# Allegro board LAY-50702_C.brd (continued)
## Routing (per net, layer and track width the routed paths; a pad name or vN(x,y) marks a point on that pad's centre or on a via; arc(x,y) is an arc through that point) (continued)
P3V3_BATT: length 17.4
  TOP w0.279: 36.67,37.83 D2.A ; D2.A 36.01,38.66 ; D2.A 36.67,39.48 ; D2.A 37.33,38.66
  BOTTOM w0.279: 38.8,33.37 BT2.1 ; BT2.1 36.78,35.08 ; BT2.1 40.82,35.08 ; BT2.1 38.8,36.8 ; 38.8,37.57 BT1.1 ; BT1.1 36.83,39.08 ; BT1.1 40.77,39.08 ; BT1.1 38.8,40.59
  vias: v1(35.65,38.66) v1(35.65,37.9) v1(35.65,37.13) v1(36.41,37.13)
P3V3_LDO: length 28
  TOP w0.381: D1.C v1(34.26,40.92)
  TOP w0.457: SH19.2 JP19.1
  L3_INT_1 w0.305: v1(34.26,40.92) v1(34.87,40.92) 36.36,39.43 53.31,39.43 JP19.1
P5V: length 53.4
  TOP w0.254: R97.1 v1(20.66,23.52) 20.66,22.94 20.1,22.39 15.76,22.39 14.43,21.06 8.15,21.06 7.73,21.48 D4.C
  TOP w0.279: 21.4,35.49 C23.1 ; C23.1 21.4,37.06 ; C23.1 20.74,36.27 ; TP7.1 21.4,34.97 ; TP7.1 20.68,34.24 ; TP7.1 22.13,34.24 ; TP7.1 21.4,33.52 ; 21.4,38 U4.3 ; U4.3 21.4,39.63 ; U4.3 20.08,38.81 ; U4.3 22.72,38.81
  L4_INT_2 w0.254: v1(22.67,34.24) v1(22.67,33.48) 22.33,33.14 22.2,33.14 21.09,32.02 21.09,30.21 21.57,29.73 21.57,27.92 20.66,27.01 v1(20.66,23.52) 20.66,22.72 20.3,22.36 20.3,18.04 22.35,15.99 v1(22.35,12.2)
  BOTTOM w0.254: SH14.1 v1(22.35,12.2)
  BOTTOM w0.279: D16.C 22.29,33.86 ; D16.C 21.63,33.04 ; D16.C 20.97,33.86 ; D16.C 21.63,34.69
P5V_CAN: length 45.1
  TOP w0.254: v1(15.8,28.9) C111.1 U20.1 15.87,27.88 15.35,27.36 15.35,26.32 15.82,25.85 C103.1 U17.1 15.82,24.83 15.7,24.72 v2(14.82,24.72) 14.13,24.72 11.48,22.07 v1(10.31,22.07)
  TOP w0.279: 15.47,35.01 U18.4 ; U18.4 15.47,37.65 ; U18.4 17.56,36.33 ; U18.4 13.39,36.33 ; 15.47,41.21 U18.2 ; U18.2 15.47,43.85 ; U18.2 14.66,42.53 ; U18.2 16.29,42.53
  L4_INT_2 w0.254: v1(15.8,28.9) 15.8,32.79 v2(18.58,35.57) v2(18.58,36.33) v2(18.58,37.09)
  BOTTOM w0.254: v1(10.31,22.07) C105.1 U19.5
  BOTTOM w0.279: v2(18.58,36.33) 18.58,37.56 ; v2(18.58,36.33) 18.58,35.1 ; v2(18.58,36.33) 19.49,36.33 ; v2(18.58,36.33) 17.66,36.33 ; D16.A 18.58,34.69 ; D16.A 18.58,33.04 ; D16.A 19.24,33.86 ; D16.A 17.92,33.86
P12V: length 17.2
  L4_INT_2 w0.279: J10.3 3.81,24.5 ; J10.3 3.81,22.41 ; J10.3 2.77,23.45 ; J10.3 4.85,23.45 ; 9.87,33.2 J9.1 ; J9.1 9.87,35.08 ; J9.1 11.81,34.14 ; J9.1 7.93,34.14
  BOTTOM w0.279: J9.1 9.87,35.08 ; J9.1 7.93,34.14 ; J9.1 11.81,34.14 ; 12.35,34.14 D8.A ; D8.A 14,34.14 ; D8.A 13.17,34.97
P12V_VBAT: length 6.3
  BOTTOM w0.279: D8.C 13.17,37.77 ; D8.C 13.17,36.12 ; D8.C 12.35,36.94 ; 13.17,37.93 C107.1 ; C107.1 13.17,39.51 ; C107.1 12.51,38.72 ; 13.17,39.58 C108.1 ; C108.1 13.17,40.65 ; C108.1 12.64,40.12
  vias: v2(13.17,43.29) v2(13.17,42.53) v2(13.17,41.77)
VBAT: length 4.9
  TOP w0.457: D2.C C25.1 40.91,41.27 40.92,41.25 JP2.1
VBAT_DCDC/VBAT_PMU: length 12.2
  TOP w0.254: C68.1 C69.1 C72.1
  TOP w0.279: U6.51 43.28,31.22 ; U6.51 43.28,29.33 ; U6.51 43.63,30.28 ; 41.5,36.65 L7.2 ; L7.2 42.92,36.65 ; L7.2 42.21,37.23 ; 43.6,34.85 C68.1 44.26,35.63 ; 43.6,32.18 C72.1 44.26,31.39 ; 44.11,28.5 U6.50 ; 44.11,28 U6.49 ; 43.72,33.45 C69.1
VBUS_USB: length 7.9
  TOP w0.254: J3.1 5.64,15.46 v2(6.21,16.03) L8.1
  BOTTOM w0.254: U9.6 2.91,15.14 3.22,15.45 5.63,15.45 v2(6.21,16.03)
VCC_IF_LINK: length 118.7
  TOP w0.254: v2(45.5,6.77) 44.74,6.01 C91.1 J5.1 46.52,2.67 47.05,2.14 52.05,2.14 52.39,2.48 v1(53.63,2.48) ; SW4.1 58.49,3.81 58.18,3.5 v2(57.69,3.5) ; U15.5 v1(33.93,34.19)
  L3_INT_1 w0.254: v2(57.69,3.5) v2(62.77,3.5) 63.92,3.5 65.79,5.36 v2(66.86,5.36) 68.86,5.36 v1(69.57,4.65) 70.72,3.5 v2(71.92,3.5)
  L4_INT_2 w0.381: v2(45.5,6.77) 45.5,10.04 45.68,10.22 v2(45.68,10.92) 45.68,34.49 46.71,35.52 48.46,35.52 50.01,37.07 50.01,39.61 48.61,41.01 JP18.2
  BOTTOM w0.254: v1(53.63,2.48) C88.1 55.01,2.85 U12.6 55.01,4.22 55.27,4.48 57.44,4.48 57.69,4.22 v2(57.69,3.5) 58.71,2.48 C93.1 59.58,2.85 U14.6 ; C90.1 69.24,2.85 U13.6 69.24,4.32 v1(69.57,4.65)
  BOTTOM w0.279: v2(66.86,5.36) 67.4,5.36 ; v2(66.86,5.36) 66.86,5.89 ; v2(66.86,5.36) 66.33,5.36
  BOTTOM w0.381: JP18.2 48.61,40.11 47.78,39.28 43.74,39.28 43.05,38.59 43.05,34.1 43.79,33.36 43.79,30.67 43.26,30.13 33.53,30.13 33.05,30.62 33.05,33.3 v1(33.93,34.19)
VCC_TGMCU: length 80.3
  TOP w0.305: U16.10 v1(40.73,7.97) ; U16.1 36.82,5.68 v2(36.56,5.42) ; v2(56.92,13.01) 55.86,13.01 55.49,13.38 R67.2 54.53,14.41 54.18,14.77 51.05,14.77 v2(50.1,15.72) ; v2(41.62,4.71) U16.7 40.73,3.59 R101.1 ; U16.15 v1(38.23,7.97)
  TOP w0.457: v2(50.61,40.85) JP18.1
  L3_INT_1 w0.305: v1(40.94,13.35) 42.61,15.02 46.89,15.02 47.57,14.33 49.99,14.33 50.34,14.69 53.97,14.69 55.66,13.01 v2(56.92,13.01) ; v1(38.23,7.97) v1(40.73,7.97)
  L4_INT_2 w0.305: v1(38.23,7.97) 38.23,6.43 37.22,5.42 v2(36.56,5.42) ; v1(40.94,13.35) 40.94,8.69 40.73,8.48 v1(40.73,7.97) 40.73,5.6 v2(41.62,4.71)
  BOTTOM w0.203: v2(56.92,13.01) U11.14
  BOTTOM w0.381: v2(50.1,15.72) 50.1,27.08 47.04,30.14 47.04,35.49 47.75,36.2 49.76,36.2 50.14,36.59 50.14,40.38 v2(50.61,40.85)
VDD_ANA: length 12
  TOP w0.254: U1.29 66.16,19.25 v1(66.3,19.11)
  L3_INT_1 w0.381: JP9.2 70.76,14.1 66.3,18.56 v1(66.3,19.11)
  BOTTOM w0.381: v1(66.3,19.11) 65.87,18.68 C34.1
VDD_CORE: length 32.3
  TOP w0.254: U1.16 60.37,15.27 C14.1 v2(59.61,13.27) ; U1.41 v1(62.37,24.3)
  L4_INT_2 w0.305: v1(62.37,24.3) 61.45,23.38 60.48,23.38 60.1,23 60.1,17.76 60.4,17.45 60.4,15.53 59.97,15.1 59.97,13.63 v2(59.61,13.27)
  BOTTOM w0.381: v1(62.37,24.3) 62.4,24.28 C16.1 C17.1 66.24,24.28 66.63,24.67 66.63,27.26 65.79,28.1 65.79,29.57 67.44,31.22 TP1.1
VDD_DCDC: length 59.6
  TOP w0.254: v2(65.92,12.22) C31.1 64.53,13.24 63.61,14.15 63.61,14.75 62.87,15.49 U1.21
  L4_INT_2 w0.381: v2(65.47,43.25) 66.5,42.21 66.5,35.52 65.26,34.27 65.26,33.03 65.86,32.43 65.86,28.24 67.09,27.01 67.09,24.6 65.59,23.1 64.78,23.1 64.3,22.62 64.3,19.06 66.45,16.91 v2(69.89,16.91) v2(71.16,16.91) 72.12,15.95 72.12,9.13 70.94,7.95 v2(69.24,7.95) 67.93,7.95 66.78,9.1 66.78,11.36 v2(65.92,12.22)
VDD_IC: length 4.7
  L4_INT_2 w0.381: JP2.2 JP2.3
  BOTTOM w0.381: JP2.3 45.19,41.25 45.21,41.27 R107.1
VDD_IO_ABC: length 11.8
  TOP w0.254: U1.4 v1(56.94,21.25)
  TOP w0.305: C32.1 56.88,24.09 v2(56.6,23.81)
  L3_INT_1 w0.254: v2(56.6,23.81) 57.41,23.81 58.1,23.12 58.1,21.82 57.53,21.25 v1(56.94,21.25) 53.39,21.25 JP8.2
VDD_LDO_CORE: length 8.2
  TOP w0.254: U1.15 v1(59.87,15.72)
  BOTTOM w0.254: v1(59.87,15.72) C35.1 58.71,14.33 58.05,14.99 C36.1 C37.1 55.45,14.99 JP4.1
VDD_MEM: length 36.9
  L3_INT_1 w0.381: v1(60.79,41.95) 62.51,41.95 63.45,41.01 v2(63.45,37.14) 67.34,37.14 v2(67.83,37.63) v2(67.83,40.67)
  BOTTOM w0.279: 63.99,37.14 v2(63.45,37.14) 63.45,36.61 ; 67.29,37.63 v2(67.83,37.63) ; v2(67.83,37.63) 67.83,37.09 ; v2(67.83,37.63) 68.36,37.63 ; C44.1 66.84,38.16 ; C44.1 65.77,38.16 ; C44.1 66.3,38.69
  BOTTOM w0.305: v1(60.79,41.95) R19.1
  BOTTOM w0.381: R19.1 52.79,41.19 51.21,39.61 51.21,35.16 50.49,34.44 JS1.1
VDD_PA_2G4: length 10.9
  TOP w0.254: U1.36 65.84,22.75 L2.1
  TOP w0.457: TP3.1 67.5,27.24 66.36,26.09 C7.1 C18.1 L2.1
  TOP w0.508: R89.1 67.83,30.67 67.5,30.34 TP3.1
VDD_REG: length 50.1
  L3_INT_1 w0.381: JP7.1 66.93,11.27 66.93,12.83 68.05,13.95 68.05,15.29 66.45,16.9 59.16,16.9 58.55,17.51 58.55,19.44 58,20 54.14,20 JP8.1
  BOTTOM w0.254: JP9.1 JP7.1
  BOTTOM w0.381: JP10.3 58.68,33.5 55.53,33.5 JP3.2 54.09,29.86 53.45,29.22 53.45,22 54.09,21.37 54.09,19.95 JP8.1
VDD_RF: length 18.3
  TOP w0.254: U1.34 v2(65.82,21.75)
  L3_INT_1 w0.254: v1(68.67,25.41) 67.07,23.81 64.57,23.81 64.22,23.45 64.22,22.05 64.52,21.75 v2(65.82,21.75)
  L4_INT_2 w0.305: v2(66.18,33.56) 68.67,31.07 v1(68.67,25.41)
VDD_SWITCH: length 9.2
  TOP w0.254: v2(56.09,22.54) C26.1 57.1,20.25 U1.6
  BOTTOM w0.381: JP1.1 56.09,25.02 55.58,24.52 55.58,23.04 v2(56.09,22.54)
VOUT_SYS/VDD_SYS: length 3.7
  TOP w0.127: U1.22 v1(63.37,15.72)
  BOTTOM w0.254: C38.1 C39.1 63.12,15.47 v1(63.37,15.72)
ADC0_A13: length 77.6
  L3_INT_1 w0.127: v1(62.37,30.55) 60.28,30.55 59.58,31.25 48.55,31.25 48.19,30.89 26.69,30.89 25.65,29.85 8.78,29.85 v1(7.11,28.18)
  BOTTOM w0.127: v1(62.37,30.55) 63.78,30.55 64.04,30.29 64.04,29.52 62.64,28.13 59.44,28.13 58.45,27.14 58.45,17.42 R8.2 ; SH2.2 v1(7.11,28.18)
ADC_IN: length 1.7
  BOTTOM w0.127: SH2.1 J1.1
ANT: length 2.3
  TOP w0.279: L3.1 L2.2 U1.35
ANT_RF: length 2
  TOP w0.279: L3.2 C1.1 L10.1
BOOT_CFG: length 7.9
  TOP w0.254: v1(53.81,4.3) 54.3,3.81 SW4.2 ; v2(51.01,8.86) 51.98,8.86 52.21,8.63 52.21,8.63 JP16.2
  L4_INT_2 w0.254: v1(53.81,4.3) 53.81,4.78 52.97,5.62 52.97,7.87 JP16.2
CAN_DIR: length 2
  TOP w0.305: U17.5 R97.2
CAN_HI: length 9.1
  TOP w0.279: v1(8.15,25.74) 8.79,26.37 R99.2
  L3_INT_1 w0.102: J10.1 3.81,27.5 3.91,27.4 4.96,27.4 6.15,26.21 6.15,25.8 6.46,25.5 7.54,25.5 7.78,25.74 v1(8.15,25.74)
  BOTTOM w0.279: v1(8.15,25.74) 8.41,25.99 U19.7
CAN_LO: length 9.1
  TOP w0.279: v1(8.15,24.98) 8.79,24.34 R45.1
  L3_INT_1 w0.102: J10.2 3.81,27.02 3.91,27.12 4.85,27.12 5.88,26.09 5.88,25.69 6.34,25.22 7.54,25.22 7.78,24.98 v1(8.15,24.98)
  BOTTOM w0.279: v1(8.15,24.98) 8.41,24.72 U19.6
CAN_RX: length 2.2
  TOP w0.279: U17.3 v1(16.2,23.83)
  BOTTOM w0.279: v1(16.2,23.83) 15.81,23.45 U19.4
CAN_TX: length 2.2
  TOP w0.279: U20.3 v1(16.2,26.88)
  BOTTOM w0.279: v1(16.2,26.88) 15.81,27.26 U19.1
CS: length 5
  BOTTOM w0.127: U5.1 63.97,39.17 64.17,38.97 64.17,38.37 63.96,38.16 R11.2 62.19,38.16 v2(61.8,37.77) R16.2
DBGIF_DETECT: length 1.4
  TOP w0.127: R81.1 U6.78
DBGIF_ISP0_CTRL: length 4.4
  TOP w0.127: U15.2 33.37,33.54 33.69,33.22 33.69,32.7 32.78,31.79 U6.72
DBGIF_RESET: length 50.3
  TOP w0.254: U6.90 v1(30.86,21.5)
  L3_INT_1 w0.127: v1(60.88,4.71) 60.58,4.4 56.03,4.4 53.92,6.51 52.37,6.51 51.49,7.4 49.99,7.4 48.69,8.7 43.71,8.7 43,9.41 37.47,9.41 36.65,8.59 31.83,8.59 31.06,7.83 v1(29.93,7.83)
  L4_INT_2 w0.127: v1(29.93,7.83) 29.93,9.43 30.86,10.36 v1(30.86,21.5)
  BOTTOM w0.127: U14.3 v1(60.88,4.71)
DBGIF_RESET_TXEN: length 55.1
  TOP w0.127: U6.71 v1(33.28,29.04)
  L3_INT_1 w0.127: v2(60.23,2.48) 59.74,1.99 45.16,1.99 44.6,2.55 36.14,2.55 35.64,3.05 v1(34.81,3.05)
  L4_INT_2 w0.127: v1(34.81,3.05) 34.51,3.35 34.51,3.35 33.76,4.1 33.76,28.55 v1(33.28,29.04)
  BOTTOM w0.127: v2(60.23,2.48) U14.5
DBGIF_TCK_SWCLK: length 56.5
  TOP w0.127: v1(42.76,31.53) 42.12,31.53 41.78,31.19 U6.54
  L3_INT_1 w0.127: v1(44.04,2.06) 45.06,1.04 63.7,1.04 64.24,1.58 64.68,1.58 v1(65.22,1.04)
  L4_INT_2 w0.127: v1(44.04,2.06) 44.53,2.55 44.53,8.16 43.82,8.87 43.82,10.63 44.69,11.49 44.69,29.6 v1(42.76,31.53)
  BOTTOM w0.127: U10.2 v1(65.22,1.04)
DBGIF_TDI: length 44.2
  TOP w0.127: U6.7 34.28,13.82 34.55,13.55 35.11,13.55 35.24,13.42 v1(35.24,13.04)
  L4_INT_2 w0.127: v1(64.41,1.04) 36.61,1.04 35.8,1.85 35.8,4.01 35.24,4.58 v1(35.24,13.04)
  BOTTOM w0.127: U10.3 64.72,1.36 v1(64.41,1.04)
DBGIF_TDO_SWO: length 49
  TOP w0.127: U6.83 v1(30.64,25)
  L3_INT_1 w0.127: v1(57.24,5.07) 55.8,5.07 54.03,6.84 52.45,6.84 51.59,7.71 50.34,7.71 49.02,9.03 44.12,9.03 43.36,9.79 37.16,9.79 36.27,8.9 31.46,8.9 v1(30.88,8.33)
  L4_INT_2 w0.127: v1(30.88,8.33) 31.86,9.3 31.86,23.79 v1(30.64,25)
  BOTTOM w0.127: U12.3 56.79,5.79 57.24,5.34 v1(57.24,5.07)
DBGIF_TMS_SWDIO: length 64.1
  TOP w0.127: U6.81 v1(30.64,26)
  L3_INT_1 w0.127: v1(71.08,4.63) 69.43,6.28 65.42,6.28 64.3,5.17 61.82,5.17 60.83,6.16 56.41,6.16 55.37,7.2 52.53,7.2 51.71,8.01 50.6,8.01 49.25,9.36 47.45,9.36 46.63,10.17 31.86,10.17 v1(30.9,9.2)
  L4_INT_2 w0.127: v1(30.9,9.2) 31.53,9.84 31.53,10.16 31.58,10.21 31.58,23.37 30.23,24.72 30.23,25.58 v1(30.64,26)
  BOTTOM w0.127: U13.3 70.54,5.17 v1(71.08,4.63)
DBGIF_TMS_SWDIO_TXEN: length 59.3
  TOP w0.127: U6.66 35.78,29.14 36.23,28.68 v1(39.3,28.68)
  L3_INT_1 w0.127: v2(69.89,2.48) 69.38,2.98 57.08,2.98 53.85,6.21 52.27,6.21 51.36,7.12 49.78,7.12 48.64,8.26 43.54,8.26 43.16,8.64 v1(40.07,8.64)
  L4_INT_2 w0.127: v1(39.3,28.68) 40.74,27.25 40.74,15.21 40.07,14.54 v1(40.07,8.64)
  BOTTOM w0.127: v2(69.89,2.48) U13.5
DBGIF_VREF: length 5.3
  TOP w0.254: U6.23 42.28,13.6 42.89,12.99 C82.1 R44.1 R43.2
DCDC_LX: length 3.8
  TOP w0.254: R1.1 62.71,14.67 62.37,15.01
  TOP w0.279: U1.20 62.37,15.01 ; L1.1 R1.1
EXTAL32K: length 3.1
  TOP w0.127: C50.1 Y2.2 69.99,15.53 69.67,15.21 R31.2
EXTAL_32M: length 1
  L3_INT_1 w0.127: v2(69.63,18.74) v2(69.63,19.76)
EXTAL_RF: length 6.3
  TOP w0.127: U1.33 65.63,21.25 65.9,20.99 v1(65.9,20.99)
  L3_INT_1 w0.127: v1(65.9,20.99) 66.32,20.99 66.53,20.78 v2(69.63,20.78) v2(71.16,20.78)
FL_USB1_DM: length 40.8
  TOP w0.241: U6.35 43.91,21 v1(43.66,21.26)
  BOTTOM w0.241: v1(43.66,21.26) 43.35,20.95 42.06,20.95 41.74,20.63 33.75,20.63 29,15.88 24.78,15.88 23.59,14.69 7.55,14.69 v2(7.23,15.02)
FL_USB1_DP: length 40.8
  TOP w0.241: U6.34 43.91,20.5 v1(43.66,20.24)
  BOTTOM w0.241: v2(7.23,13.96) 7.55,14.28 23.76,14.28 24.95,15.48 29.17,15.48 33.92,20.23 41.91,20.23 42.23,20.55 43.35,20.55 v1(43.66,20.24)
FL_USB_5V0: length 59.4
  TOP w0.279: 10.88,17.1 C75.1 ; C75.1 9.91,17.76 ; C75.1 11.86,17.76 ; v2(12.79,15.85) 12.79,16.9 ; v2(12.79,15.85) 13.28,15.85 ; v2(12.79,15.85) 12.79,14.81 ; D4.A 7.73,19.79 ; D4.A 6.91,19.13 ; D4.A 8.56,19.13 ; D4.A 7.73,18.47 ; C76.1 13.58,17.76 ; C76.1 12,17.76 ; C76.1 12.79,17.1 ; 7.73,16.91 L8.2 ; L8.2 8.36,17.43 ; L8.2 7.11,17.43 ; L8.2 7.73,17.95
  L4_INT_2 w0.305: v2(12.79,15.85) 11.05,15.85 10.45,15.25 10.45,13.45 v2(9.79,12.79)
  BOTTOM w0.305: v1(14.06,17.76) 14.72,17.1 25.86,17.1 26.8,18.04 26.8,21.95 29.14,24.29 42.73,24.29 44.64,26.2 47.2,26.2 47.69,25.71 v2(47.69,24.47)
H/RST: length 3
  BOTTOM w0.127: R18.2 R20.2 66.8,39.67 U5.7
HW_VER_1: length 3.1
  TOP w0.127: R102.1 31.86,32.39 31.86,32.39 32.28,31.97 U6.73
HW_VER_2: length 4.3
  TOP w0.127: U6.65 36.28,31.83 36.74,32.29 38.19,32.29 38.29,32.39 R104.1
HW_VER_3: length 2.1
  TOP w0.127: U6.1 31.28,13.52 31.02,13.26 R105.1
HW_VER_4: length 6.6
  TOP w0.127: R106.1 44.46,15.75 44,16.21 44,18.86 44.14,19 U6.31
HW_VER_6: length 43.7
  TOP w0.127: U6.56 v1(40.78,31.45)
  L4_INT_2 w0.127: JP21.2 47.4,36.36 45.85,36.36 44.78,37.42 42.83,37.42 40.78,35.37 v1(40.78,31.45) 40.78,29.14 43.11,26.8 v1(43.11,6.18)
  BOTTOM w0.127: Q3.1 43.62,7.53 43.11,7.02 v1(43.11,6.18)
HW_VER_7: length 36.6
  TOP w0.127: U6.27 v1(46.27,17) ; JP22.2 65.31,7.31 65.68,6.94 65.69,6.94 66.05,6.58 v1(66.05,3.87)
  L3_INT_1 w0.127: v1(64.62,15.74) 63.42,14.54 59,14.54 57.58,15.96 56.31,15.96 55.42,16.85 49.48,16.85 49.33,17 v1(46.27,17)
  L4_INT_2 w0.127: JP22.2 65.31,11.44 64.62,12.13 v1(64.62,15.74)
  BOTTOM w0.127: v1(66.05,3.87) 64.63,3.87 64.22,4.28 U10.5
HW_VER_8: length 3.7
  TOP w0.127: R96.1 42.21,32.26 41.28,31.33 U6.55
IF_DETECT: length 52.1
  L3_INT_1 w0.127: v1(30.88,7.3) 31.44,7.3 32.26,8.11 34.7,8.11 35.8,7.01 40.52,7.01 41.4,7.88 48.41,7.88 49.45,6.84 51.21,6.84 53.05,5 v2(53.05,4.3)
  L4_INT_2 w0.127: v2(28.08,28.52) 28.08,26.19 31.28,23 31.28,10.27 30.39,9.38 30.39,7.79 v1(30.88,7.3)
  BOTTOM w0.127: v2(53.05,4.3) 52.36,4.3 J5.9 D14.C
IF_ISPEN: length 41.9
  L3_INT_1 w0.127: J5.7 49.69,4.17 46.13,4.17 45.74,3.79 v1(43.62,3.79)
  L4_INT_2 w0.127: v1(43.62,3.79) 43.62,5.01 42.68,5.95 42.68,26.53 38.24,30.97 38.24,31.92 37.57,32.59 37.57,32.59 v2(37.28,32.89)
  BOTTOM w0.127: J5.7 49.44,2.65 48.9,2.65 48.46,2.2 D13.C
IF_TCK_SWDCLK: length 34.8
  TOP w0.127: v2(62.04,5.67) 61.42,6.28 52.15,6.28 51.94,6.49 48.7,6.49 47.79,5.57 J5.4
  L3_INT_1 w0.127: v2(62.04,5.67) 61.14,6.56 56.67,6.56 55.96,7.27 55.96,8.59 55.4,9.15 v1(53.92,9.15)
  BOTTOM w0.127: D15.5 48.71,9.51 48.42,9.22 48.42,7.32 47.79,6.69 R79.1 J5.4 ; v1(53.92,9.15) 53.92,10.96 54.48,11.51 U11.3
IF_TDI: length 23.5
  TOP w0.127: J5.8 50.33,5.57 50.91,6.16 51.82,6.16 52.02,5.95 60.73,5.95 v2(62.04,4.65)
  L4_INT_2 w0.127: J5.8 50.33,6.69 49.87,7.15 49.87,9.24 50.33,9.7 v1(50.33,10.79)
  BOTTOM w0.127: D15.3 47.9,10.16 48.97,11.22 49.9,11.22 v1(50.33,10.79)
IF_TDO_SWO: length 28.8
  L4_INT_2 w0.127: v1(48.29,14.97) 49.41,13.85 v1(49.41,10.79) 49.41,9.73 49.06,9.38 J5.6 49.69,4.17 49.69,2.67 50.37,1.99 56.15,1.99 v2(56.68,1.46)
  BOTTOM w0.127: D15.4 49.41,10.28 v1(49.41,10.79) ; U11.11 54.88,14.14 54.15,14.87 51.1,14.87 51,14.97 v1(48.29,14.97)
IF_TMS_SWDIO: length 53.9
  TOP w0.127: v2(46.52,6.77) J5.2
  L3_INT_1 w0.127: v2(46.52,6.77) 47.85,6.77 48.56,6.07 v1(49.91,6.07) ; v1(46.61,11.84) 47.83,13.06 54.2,13.06 55.07,12.2 v1(58.09,12.2) 58.49,11.79 59.62,11.79 61.07,10.35 65.03,10.35 66.66,8.72 69.85,8.72 72.81,5.76 72.81,2.5 71.77,1.46 v2(70.9,1.46)
  L4_INT_2 w0.127: v1(46.61,11.84) 46.61,9.28 46.02,8.69 46.02,5.3 J5.2
  BOTTOM w0.127: D15.6 49.28,6.7 v1(49.91,6.07) ; v1(58.09,12.2) 56.88,12.2 56.47,12.61 U11.15
IF_TRGRST_SWDRST: length 31.8
  L3_INT_1 w0.127: J5.10 50.68,5.73 50.68,6.18 50.35,6.51 48.87,6.51 v1(47.91,7.46) ; v1(47.25,13.09) 47.58,13.42 50.93,13.42 v1(51.61,14.11)
  L4_INT_2 w0.127: J5.10 52.25,4.16 52.25,3.79 52.55,3.49 56.11,3.49 58.13,1.46 v2(61.25,1.46) ; v1(47.25,13.09) 47.25,11.87 47.91,11.2 v1(47.91,7.46)
  BOTTOM w0.127: v1(51.61,14.11) 51.61,13.42 52.02,13.01 52.95,13.01 U11.7 ; D15.1 47.79,8.86 47.91,8.73 v1(47.91,7.46)
L_R1: length 1.2
  TOP w0.127: LED1.A R22.2
L_Y2: length 1.2
  TOP w0.127: LED2.A R23.2
LED1_R: length 2.3
  TOP w0.127: LED1.C v1(6.85,1.82)
  BOTTOM w0.127: v1(6.85,1.82) 7.38,1.29 Q1.3
LED1_R1: length 2.3
  BOTTOM w0.127: R26.2 R28.2 Q1.1
LED2_Y: length 2.3
  TOP w0.127: LED2.C v1(5.45,1.82)
  BOTTOM w0.127: v1(5.45,1.82) 4.92,1.29 Q2.3
LED2_Y2: length 2.3
  BOTTOM w0.127: R27.1 R29.2 Q2.1
LED_RST: length 1.2
  TOP w0.305: R24.2 D3.A
LLWU/NMI_B: length 1.8
  BOTTOM w0.127: J2.2 SH5.2
LPI2C1_SCL: length 1.8
  BOTTOM w0.127: J2.5 SH11.2
LPI2C1_SDA: length 1.9
  BOTTOM w0.127: J2.6 SH13.2
LPSPI1_PSC0: length 1.7
  BOTTOM w0.127: SH4.1 J1.3
LPSPI1_SCK: length 1.7
  BOTTOM w0.127: SH6.1 J1.4
LPSPI1_SIN: length 1.7
  BOTTOM w0.127: SH8.1 J1.5
LPSPI1_SOUT: length 1.7
  BOTTOM w0.127: SH10.1 J1.6
LPUART0_RX: length 1.8
  BOTTOM w0.127: J2.3 SH7.2
LPUART0_TX: length 1.8
  BOTTOM w0.127: J2.4 SH9.2
MCU_LINK_3V3: length 83.1
  TOP w0.254: v2(28.08,18.02) 28.1,18.04 28.1,18.11 28.49,18.5 U6.96 ; v2(36,12.28) 36,12.94 36.46,13.39 37.74,13.39 38.28,13.93 U6.15 ; U6.95 v2(28.08,19) ; U6.75 v2(31.28,31.71) ; v2(37.28,31.71) U6.63 ; U6.38 46.24,22.5 v2(46.54,22.19) ; v2(28.08,25) 28.58,24.5 U6.84 ; U6.44 46.29,25.5 v2(46.54,25.24) ; v2(34.28,31.71) U6.69
  TOP w0.279: 21.87,14.3 L4.2 ; L4.2 22.44,13.59 ; L4.2 23.01,14.3 ; 26.25,13.4 C51.1 ; C51.1 25.46,14.06 ; C51.1 27.04,14.06 ; C54.1 25.32,14.06 ; C54.1 24.35,13.4 ; C54.1 23.37,14.06
  L3_INT_1 w0.381: v2(46.67,14.31) 43.82,14.31 41.79,12.28 v2(36,12.28) v1(28.08,12.28) ; v2(37.28,31.71) v2(34.28,31.71) v2(31.28,31.71)
  L4_INT_2 w0.381: v1(28.08,12.28) v2(28.08,18.02) v2(28.08,19) v2(28.08,25) 27.09,25.99 27.09,29.2 28.63,30.74 30.31,30.74 v2(31.28,31.71) ; v2(46.67,14.31) 47.35,14.99 47.35,18.42 46.54,19.23 v2(46.54,22.19) 47.12,22.78 47.12,24.66 v2(46.54,25.24)
MCU_LINK_N_16MHZ: length 6.1
  TOP w0.127: C78.1 Y4.1 47.42,18.39 46.53,17.5 U6.28
MCU_LINK_P_16MHZ: length 7.2
  TOP w0.127: U6.29 46.25,18 46.95,18.7 46.95,19.83 47.51,20.39 Y4.2 C77.1
MCU_LINK_RST: length 37.7
  TOP w0.127: U6.32 44.22,19.5 43.53,18.82 v1(43.53,16.47)
  L3_INT_1 w0.127: v1(43.53,16.47) 42.04,16.47 39.83,14.26 26.55,14.26 v1(24.49,12.2)
  L4_INT_2 w0.127: v1(24.49,12.2) 24.49,15.59 21.93,18.14 21.93,23.06 J4.10
MCU_LNK_RX: length 27
  TOP w0.127: v1(37.86,27.91) 35.02,27.91 33.78,29.16 U6.70 ; v1(39.23,8.64) U16.13
  L4_INT_2 w0.127: v1(39.23,8.64) 39.23,14.74 38.8,15.17 38.8,26.97 v1(37.86,27.91)
MCU_LNK_TX: length 28.7
  TOP w0.127: U6.79 33.96,27 34.33,27.36 v1(36.79,27.36) ; v1(38.23,8.64) 38.73,8.14 U16.14
  L4_INT_2 w0.127: v1(36.79,27.36) 37.2,27.36 37.78,26.78 37.78,9.09 v1(38.23,8.64)
MCULINK_VDDA: length 6.6
  TOP w0.254: U6.16 C64.1 C63.1 38.78,10.16 38.9,10.04 R33.1 L5.2
MLINK_3V3: length 150.3
  TOP w0.279: 19.42,15.58 R34.2 18.63,16.25 ; C53.1 20.54,16.25 ; C53.1 19.56,15.58 ; C53.1 21.51,15.58 ; 23.8,17.86 J4.1 24.52,18.58 ; L4.1 23.01,15.99 ; L4.1 21.87,15.99 ; L4.1 22.44,16.7
  TOP w0.305: v1(55.07,6.71) 52.35,6.71 52.17,6.89 47.63,6.89 v1(47.06,7.46) ; v2(36.56,6.43) 36.82,6.18 U16.16 ; R50.1 v1(8.97,6.52)
  TOP w0.381: v2(30.25,32.98) 30.25,34.71 31.8,36.25 37.74,36.25 38.14,36.65 L7.1
  L3_INT_1 w0.305: v1(23.62,32.98) v2(30.25,32.98) ; v1(47.06,7.46) 41.86,7.46 40.83,6.43 v2(36.56,6.43) 19.64,6.43 19.2,6.88 9.33,6.88 v1(8.97,6.52) ; v1(19.39,21.12) 12.56,21.12 11.16,19.72 v1(9.41,19.72)
  L4_INT_2 w0.305: J4.1 24.75,19.53 24.75,24.44 24.13,25.06 v1(23.62,25.06) v1(23.62,32.98) ; v1(9.41,19.72) 9.41,15.93 8.36,14.89 8.36,7.12 v1(8.97,6.52) ; v2(35.96,9.46) 36.56,8.86 v2(36.56,6.43) ; v2(66.86,2.36) 68.21,3.71 68.21,5.91 v2(69.24,6.94)
  BOTTOM w0.279: 66.33,2.36 v2(66.86,2.36) ; v2(66.86,2.36) 66.86,1.83 ; v2(66.86,2.36) 67.4,2.36
  BOTTOM w0.305: R46.1 v1(19.39,21.12) ; U13.1 v2(69.24,6.94) C92.1 U14.1 58,5.79 57.08,6.71 v1(55.07,6.71) 54,6.71 C87.1 54.03,6.31 54.54,5.79 U12.1 ; R47.1 v1(19.31,18.58) ; R48.1 v1(23.62,25.06) ; C83.1 J4.1
MLINK_FB: length 16.9
  TOP w0.127: U6.39 43.91,23 43.55,23.36 43.55,25.64 43.91,26 U6.45 46.2,26 46.45,26.26 C66.1 C65.1 49.05,26.26 49.31,25.99 49.31,24.99 49.44,24.86 L6.2 52,23.73 52.23,23.5 52.87,23.5 53.05,23.33 C67.1
MLINK_LX: length 7.4
  TOP w0.127: U6.48 45.94,27.5 47.11,28.67 L6.1
P_LED: length 17.8
  TOP w0.127: JS2.1 20.35,5.67 20.35,5.9 19.13,7.12 7.44,7.12 R22.1 R23.1 R25.1
P_VDD_SWITCH: length 18.4
  TOP w0.305: JP3.1 52.09,31.09 52.64,30.54 55.06,30.54 JP1.2
  TOP w0.381: v2(45.85,40.25) 46.66,39.43 50.14,39.43 50.8,38.77 50.8,33.34 JP3.1
PIO0_5-ISP_EN: length 1.7
  BOTTOM w0.305: R51.2 J4.7
PIO0_5-ISP_EN-LED_SWD_ACT: length 52.6
  TOP w0.254: v1(30.7,22.5) U6.88
  TOP w0.305: v1(9.94,1.61) 8.55,1.61 8.24,1.91 D7.C ; U6.88 26.86,22.5 v2(25.45,23.91)
  L3_INT_1 w0.305: v1(9.94,1.61) 10.7,0.85 27.66,0.85 v1(28.42,1.61)
  L4_INT_2 w0.305: v1(30.7,22.5) 29.75,21.56 29.75,10.94 28.42,9.61 v1(28.42,1.61)
  BOTTOM w0.305: v2(25.45,23.91) R48.2 25.45,25.69 JP12.2
PIO0_10-SWO: length 32.4
  TOP w0.127: U6.21 v1(41.28,16.45)
  L3_INT_1 w0.127: v1(23.77,12.2) 26.09,14.51 39.33,14.51 v1(41.28,16.45)
  L4_INT_2 w0.127: v1(23.77,12.2) 23.77,15.56 21.55,17.79 21.55,20.7 v2(21.13,21.12)
  BOTTOM w0.127: J4.6 v2(21.13,21.12)
PIO0_11-SWDCLK: length 21.3
  TOP w0.127: U6.13 37.28,16.26 36.41,17.13 35.67,17.13 35.24,17.55 v1(35.24,18.44)
  L3_INT_1 w0.127: v2(21.13,19.85) 21.8,19.19 24.87,19.19 25.11,19.42 34.26,19.42 v1(35.24,18.44)
  BOTTOM w0.127: J4.4 v2(21.13,19.85)
PIO0_12-SWDIO: length 20.3
  TOP w0.127: v1(34.23,18.44) 34.23,17.38 35.03,16.57 36.1,16.57 36.78,15.89 U6.12
  L3_INT_1 w0.127: v2(21.13,18.58) 21.73,17.98 26.72,17.98 27.17,18.44 v1(34.23,18.44)
  BOTTOM w0.127: J4.2 v2(21.13,18.58)
PO_LED: length 1.2
  TOP w0.127: LED3.A R25.2
PTA0/SWD_DIO: length 14.1
  TOP w0.127: U1.8 v1(57.35,19.25)
  L4_INT_2 w0.127: v1(57.35,19.25) 57.77,19.25 58.12,18.89 58.12,17.08 58.45,16.75 58.45,13.37 57,11.91 57,10.7 v1(56.57,10.27)
  BOTTOM w0.127: v1(56.57,10.27) 56.95,10.65 56.95,11.67 56.41,12.21 U11.16
PTA1/SWD_CLK: length 13.2
  TOP w0.127: v1(53.52,11.74) R66.1 ; U1.9 v1(56.89,18.75)
  L4_INT_2 w0.127: v1(53.52,11.74) 53.52,13.01 55.7,15.2 56.69,15.2 57.41,15.92 57.41,17.1 57.82,17.51 57.82,18.25 57.31,18.75 v1(56.89,18.75)
  BOTTOM w0.127: v1(53.52,11.74) 53.81,11.45 53.97,11.45 54.08,11.55 U11.4
PTA4/SWO/BOOT_CFG: length 15
  TOP w0.127: U1.10 56.94,18.25 56.42,17.73 56.42,17.18 56.52,17.08 56.52,17.08 56.9,16.69 56.9,15.93 56.27,15.3 v1(56.27,14.05)
  L4_INT_2 w0.127: JP16.1 54.92,7.92 54.97,7.92 55.93,8.88 55.93,10.25 56.64,10.96 56.64,11.79 56.27,12.17 v1(56.27,14.05)
  BOTTOM w0.127: v1(56.27,14.05) 55.94,14.39 55.4,14.39 55.28,14.27 U11.12
PTA16: length 74.4
  TOP w0.127: U1.11 v1(57.35,17.75)
  L3_INT_1 w0.127: v1(11.23,10.5) 11.23,11.23 13.06,13.06 15.1,13.06 16.42,11.74 17.6,11.74 22.2,16.34 36.96,16.34 37.75,17.13 37.75,17.56 38.08,17.89 49.68,17.89 50.22,17.36 55.73,17.36 56.12,17.75 v1(57.35,17.75)
  L4_INT_2 w0.127: JP13.3 53.12,34.42 53.12,30.34 54.13,29.33 54.13,19.01 54.69,18.45 55.83,18.45 56.53,17.75 v1(57.35,17.75)
  BOTTOM w0.127: v1(11.23,10.5) 11.23,11.07 11.68,11.52 SH7.1
PTA17: length 72.4
  TOP w0.127: U1.12 v1(56.94,17.25)
  L3_INT_1 w0.127: v1(15.41,11.52) 15.93,10.99 18.05,10.99 18.67,11.62 20.38,11.62 24.39,15.63 37.32,15.63 38.62,16.92 41.61,16.92 42.17,17.48 49.56,17.48 49.94,17.1 55.96,17.1 56.1,17.25 v1(56.94,17.25)
  L4_INT_2 w0.127: v1(56.94,17.25) 53.95,17.25 53.53,17.68 53.53,29.08 51,31.61 51,35.54 52.43,36.97 JP14.3
  BOTTOM w0.127: SH9.1 v1(15.41,11.52)
PTA18: length 34
  TOP w0.127: U1.13 v1(58.87,15.72) ; U2.17 76.65,24.98 76.52,25.11 v1(76.15,25.11)
  L3_INT_1 w0.127: v1(60.87,28.61) 62,27.49 68.71,27.49 69.46,28.24 v1(71.23,28.24)
  L4_INT_2 w0.127: v1(60.87,28.61) 60.27,28.02 60.27,27.59 58.48,25.8 58.48,17.36 58.87,16.96 v1(58.87,15.72)
  BOTTOM w0.127: v1(76.15,25.11) 75.49,25.11 74.15,26.45 74.15,27.64 73.56,28.24 C100.1 R94.1 v1(71.23,28.24)
PTA19: length 34.8
  TOP w0.127: U1.14 v1(59.37,15.32) ; U2.18 75.79,24.4 R91.2 v2(73.99,25.19)
  L3_INT_1 w0.127: v1(72.52,29.02) 72.21,28.71 68.92,28.71 68.03,27.82 62.67,27.82 v1(61.87,28.61)
  L4_INT_2 w0.127: v1(72.52,29.02) 73.34,29.02 73.99,28.38 v2(73.99,25.19) ; v1(59.37,15.32) 59.37,17.07 58.88,17.56 58.88,25.63 v1(61.87,28.61)
PTA20: length 40.1
  TOP w0.127: U2.19 74.41,23.75 v2(72.97,25.19) ; U1.17 v1(60.87,15.32)
  L3_INT_1 w0.127: v1(72.72,30.04) 71.8,29.12 68.64,29.12 67.77,28.25 66.1,28.25 65.74,28.61 v1(63.84,28.61)
  L4_INT_2 w0.127: v1(63.84,28.61) 63.02,27.79 63.02,24.27 61.11,22.36 61.11,16.38 60.87,16.14 v1(60.87,15.32)
  BOTTOM w0.127: v1(72.72,30.04) 72.1,29.42 69.76,29.42 68.61,28.28 68.61,26.55 69.98,25.19 R95.1 v2(72.97,25.19)
PTA21: length 2.6
  TOP w0.127: v1(61.37,15.72) U1.18
  BOTTOM w0.127: R8.1 U1.18 v1(61.37,15.72)
PTB0: length 63.6
  TOP w0.127: v1(59.87,30.06) U1.46
  L3_INT_1 w0.127: v1(59.87,30.06) 59.21,30.72 54.11,30.72 53.78,30.39 26.9,30.39 25.86,29.35 13.35,29.35 v1(12.19,28.18)
  L4_INT_2 w0.127: v1(59.87,30.06) 61.07,31.25 61.07,33.66 60.79,33.95 v1(60.79,35.74)
  BOTTOM w0.127: R16.1 v1(60.79,35.74) ; SH4.2 v1(12.19,28.18)
PTB1: length 68.1
  TOP w0.127: v1(59.77,39.16) 58.72,38.11 58.72,29.81 59.37,29.16 v1(59.37,25.19) U1.47
  L3_INT_1 w0.127: v1(22.35,28.18) 26.8,28.18 27.49,27.49 v1(33.21,27.49) ; v1(59.37,25.19) 52.24,25.19 48.78,21.73 45.35,21.73 44.84,22.23 42.88,22.23 41.3,20.65 34.05,20.65 v1(33.21,21.48)
  L4_INT_2 w0.127: v1(33.21,27.49) v1(33.21,21.48)
  BOTTOM w0.127: v1(22.35,28.18) 19.98,28.18 SH8.2 ; R13.1 v1(59.77,39.16)
PTB2: length 75.5
  TOP w0.127: U1.48 58.87,27.52 v1(57.78,28.61) ; v2(69.86,39.66) 70.59,38.92 70.59,33.94 71.3,33.24 v1(71.3,30.04)
  L3_INT_1 w0.127: v1(71.3,30.04) 69.72,30.04 69.22,30.54 63.05,30.54 62.57,30.06 62.26,30.06 61.78,29.57 58.74,29.57 v1(57.78,28.61) 54.92,28.61 53.4,30.13 27,30.13 25.96,29.09 16.75,29.09 15.84,28.18 v1(14.73,28.18)
  BOTTOM w0.127: SH6.2 v1(14.73,28.18)
PTB3: length 73
  TOP w0.127: v1(57.78,27.9) 58.25,27.43 58.25,24.37 57.44,23.55 57.44,22.85 57.54,22.75 U1.1 ; v2(69.86,40.67) 70.95,39.58 70.95,34.27 72.01,33.21 v1(72.01,30.04)
  L3_INT_1 w0.127: v1(20.83,28.61) 25.84,28.61 27.11,29.88 53.2,29.88 54.85,28.23 57.46,28.23 v1(57.78,27.9) 59.27,27.9 60.41,29.04 63.2,29.04 64.26,30.09 68.88,30.09 69.45,29.53 71.5,29.53 v1(72.01,30.04)
  BOTTOM w0.127: SH10.2 v1(20.83,28.61)
PTB4: length 90.4
  TOP w0.127: v2(61.8,36.75) 60.06,36.75 v1(59.27,37.55) ; U1.2 v1(56.94,22.25)
  L3_INT_1 w0.127: v1(56.94,22.25) 56.64,22.55 56.64,22.95 56.34,23.25 51.32,23.25 48.83,20.76 43.11,20.76 42.27,19.92 25.08,19.92 24.52,20.48 15.36,20.48 v1(14.73,19.85) ; v2(69.86,38.64) 69.86,37.88 68.1,36.13 62.43,36.13 v2(61.8,36.75)
  L4_INT_2 w0.127: v1(14.73,19.85) 14.73,13.74 13.62,12.63 13.62,6.06 JP24.3 ; v1(56.94,22.25) 57.67,22.98 57.67,25.87 58.99,27.19 58.99,33.28 59.27,33.56 v1(59.27,37.55)
PTB5: length 67.9
  TOP w0.127: U1.3 v1(57.35,21.75)
  L3_INT_1 w0.127: v1(57.35,21.75) 52,21.75 49.23,18.98 37.07,18.98 36.76,18.68 36.76,17.81 36,17.05 22.13,17.05 v1(17.27,12.2)
  L4_INT_2 w0.127: v1(58.75,40.17) 59.27,39.66 59.27,38.62 59.72,38.16 59.72,33.28 59.37,32.93 59.37,27.12 58.07,25.82 58.07,22.48 v1(57.35,21.75)
  BOTTOM w0.127: R15.1 v1(58.75,40.17) ; SH11.1 v1(17.27,12.2)
PTC0: length 79.9
  TOP w0.127: U1.37 64.37,24.35 64.68,24.66 v1(64.68,25.19)
  L3_INT_1 w0.127: JP23.3 14.56,3.95 30.56,3.95 31.42,4.81 33.48,4.81 33.93,4.35 35.41,4.35 35.84,3.92 40.49,3.92 41.48,2.93 45.42,2.93 46,2.35 52.6,2.35 54.44,4.19 v1(54.44,4.81)
  L4_INT_2 w0.127: v1(54.44,4.81) 56.18,6.55 56.18,9.41 56.54,9.76 58.7,9.76 60.35,11.41 60.35,12.4 62.18,14.23 62.18,22.69 v1(64.68,25.19)
  BOTTOM w0.127: JP23.3 12.73,3.06 12.53,3.26 11.71,3.26 10.44,4.53 10.44,5.19 10.05,5.58 R26.1
PTC1: length 25.5
  TOP w0.127: v2(63.82,42.23) R9.2 C45.1 TP9.1 ; U1.38 v1(63.87,25.19)
  L4_INT_2 w0.127: v2(63.82,42.23) 63.82,38.81 64.41,38.21 64.41,36.81 63.04,35.44 63.04,31.17 64.26,29.96 64.26,28.02 63.87,27.64 v1(63.87,25.19)
PTC2: length 18.7
  TOP w0.127: v1(63.37,30.04) C21.1 U1.39
  L4_INT_2 w0.127: JP13.1 58.19,34.43 58.19,30.86 v1(57.36,30.04)
  BOTTOM w0.127: v1(63.37,30.04) 62.24,30.04 61.78,29.57 58.71,29.57 58.24,30.04 v1(57.36,30.04)
PTC3: length 20.8
  TOP w0.127: v1(62.37,29.53) C22.1 62.87,25.83 U1.40
  L4_INT_2 w0.127: JP14.1 57.51,36.89 58.61,35.8 58.61,30.35 v1(57.78,29.53)
  BOTTOM w0.127: v1(62.37,29.53) 61.98,29.14 58.17,29.14 v1(57.78,29.53)
PTC4: length 47.5
  TOP w0.279: v1(62.01,25.19) 62.01,24.78 61.87,24.64 U1.42
  L3_INT_1 w0.102: v1(62.01,25.19) 62.01,25.56 61.76,25.81 61.76,26.07 61.33,26.5 43.89,26.5 41.72,24.33 27.5,24.33 27.2,24.62 22.78,24.62 22.42,24.98 19.75,24.98 19.65,25.08 v2(19.65,26.37)
PTC5: length 47.1
  TOP w0.279: U1.43 61.37,24.64 61.24,24.78 v1(61.24,25.19)
  L3_INT_1 w0.102: v1(61.24,25.19) 61.24,25.56 61.48,25.81 61.48,25.95 61.21,26.22 44.01,26.22 41.84,24.05 27.38,24.05 27.09,24.34 22.67,24.34 22.31,24.7 19.75,24.7 19.65,24.6 v2(19.65,23.32)
PTC6: length 75.4
  TOP w0.127: U1.44 v1(60.87,24.3)
  L3_INT_1 w0.127: v1(6.26,21.4) 10.52,21.4 11.44,22.31 20.94,22.31 21.62,22.99 25.15,22.99 25.46,23.3 33.38,23.3 33.74,22.94 41.97,22.94 42.73,23.71 48.6,23.71 50.6,25.71 60.57,25.71 60.79,25.48 60.79,24.84 60.87,24.76 v1(60.87,24.3)
  L4_INT_2 w0.127: v1(6.26,21.4) 6.26,18.91 5.47,18.12 5.47,9.87 v1(4.32,8.72)
  BOTTOM w0.127: R27.2 v1(4.32,8.72)
PTC7: length 92.4
  TOP w0.127: U1.45 v1(60.37,25.19) 60.37,30.21 59.11,31.48 59.11,35.09 60.3,36.28 66.55,36.28 66.98,36.71 66.98,38.79 TP12.1 68.35,40.16 68.35,41.4 68.67,41.71 C46.1 R17.2 SW3.2
  L3_INT_1 w0.127: v1(13.22,21.72) 24.98,21.72 26.42,20.28 41.84,20.28 43.26,21.7 44.51,21.7 44.97,21.24 48.83,21.24 52.33,24.74 59.92,24.74 v1(60.37,25.19)
  L4_INT_2 w0.127: v1(8.97,11.52) 8.97,13.62 9.71,14.36 9.71,15.32 10.35,15.96 10.35,18.85 v1(13.22,21.72)
  BOTTOM w0.127: SH5.1 v1(8.97,11.52)
PTD2: length 63.1
  TOP w0.127: v1(65.9,15.17) 65.9,17.06 65.71,17.25 U1.25
  L3_INT_1 w0.127: v1(65.9,15.17) 65.1,15.17 64.06,14.13 58.7,14.13 57.23,15.6 56.13,15.6 55.14,16.59 48.89,16.59 48.23,15.93 42.04,15.93 40.11,14 27.13,14 24.39,11.26 21.11,11.26 20.5,10.65 v1(19,10.65)
  L4_INT_2 w0.127: JP23.1 19,4.38 v1(19,10.65)
PTD2/TMP1_CH0: length 10.1
  BOTTOM w0.127: JP23.2 14.73,3.51 14.38,3.87 11.99,3.87 11.07,4.78 11.07,6.01 10.14,6.94 SH3.1
PTD3: length 61.5
  TOP w0.127: U1.26 65.73,17.75 66.33,17.15 66.33,14.98 v1(66.71,14.6)
  L3_INT_1 w0.127: v1(66.71,14.6) 65.39,14.6 64.54,13.75 58.47,13.75 57.07,15.15 48.98,15.15 48.6,15.53 42.15,15.53 40.37,13.75 27.62,13.75 24.67,10.8 21.39,10.8 20.62,10.04 v1(18.29,10.04)
  L4_INT_2 w0.127: v1(18.29,10.04) 18.29,6.72 JP24.1
PTD3/I2C1_SDA: length 5.5
  BOTTOM w0.127: SH13.1 15.26,6.87 14.73,6.33 JP24.2
PTD4_XTAL32K: length 6
  TOP w0.127: R30.1 67.6,14.96 67.6,15.35 67.09,15.86 67.09,17.6 66.44,18.25 U1.27
PTD5_EXTAL32K: length 5.6
  TOP w0.127: U1.28 66,18.75 66.14,18.6 66.56,18.6 67.42,17.74 67.42,16 R31.1
PWM/TMP1_CH0: length 1.8
  BOTTOM w0.127: SH3.2 J2.1
RESET: length 1.7
  BOTTOM w0.127: SH1.1 J1.2
RF1: length 2.3
  TOP w0.279: U2.14 R110.1 R92.1
RF4: length 2.3
  TOP w0.279: U2.5 C98.1 R93.1
RF_50: length 2
  TOP w0.279: C3.1 C2.1 L10.2
RF_A: length 16.5
  TOP w0.279: U2.11 79.75,23.25 arc(81.86,24.12) 82.73,26.23 arc(83.06,27.67) 83.89,28.89 C9.1 L11.1
RF_ANT_1: length 3.1
  TOP w0.279: E1.1 C10.1 L11.2
RF_ANT_2: length 3.1
  TOP w0.279: E2.1 C12.1 L12.2
RF_B: length 16.5
  TOP w0.279: L12.1 C11.1 83.89,16.11 arc(83.06,17.33) 82.73,18.77 arc(81.86,20.88) 79.75,21.75 U2.8
RF_SMA_1: length 2.4
  TOP w0.279: J7.1 C97.1 R92.2
RF_SMA_2: length 2.4
  TOP w0.279: R93.2 C99.1 J8.1
RST_TGTMCU_B: length 104.7
  TOP w0.127: SW1.2 69.69,3.81 70.33,4.45 70.33,5.69 71.51,6.87 73.74,6.87 74.48,7.6 74.48,10.8 JP11.2 ; U1.23 63.87,15.21 65.06,14.03 v1(65.9,14.03)
  L3_INT_1 w0.127: v1(49.74,30.83) 49.32,30.83 49.13,30.64 26.79,30.64 25.75,29.6 11.07,29.6 v1(9.65,28.18) ; v1(52.88,14.11) 53.54,13.45 54.46,13.45 55.35,12.56 57.61,12.56 57.9,12.85 64.72,12.85 v1(65.9,14.03)
  L4_INT_2 w0.127: JP25.2 54.02,11.31 53.31,11.31 53.09,11.54 53.09,12.66 52.88,12.86 v1(52.88,14.11) 52.88,14.56 52.65,14.79 51.89,14.79 51.51,15.17 51.51,16.27 49.74,18.04 v1(49.74,30.83)
  BOTTOM w0.127: JP11.2 71.25,14.03 v1(65.9,14.03) ; SH1.2 v1(9.65,28.18)
RST_U11: length 5.9
  L4_INT_2 w0.127: v1(52.25,14.11) 52.25,12.86 52.1,12.71 52.1,11.23 JP25.1
  BOTTOM w0.127: v1(52.25,14.11) 52.25,13.65 52.49,13.41 52.95,13.41 U11.8
SCK: length 6.9
  L3_INT_1 w0.127: v2(68.84,39.66) 69.35,40.17 71.26,40.17 71.6,39.82 v2(71.6,38.77)
  BOTTOM w0.127: v2(68.84,39.66) R10.2 67.31,40.17 U5.6
SI: length 9.7
  L3_INT_1 w0.127: v2(68.84,40.67) 69.45,41.28 72.58,41.28 73.03,40.83 v2(73.03,38.77)
  BOTTOM w0.127: v2(68.84,40.67) 68.26,41.26 67.47,41.26 66.89,40.67 U5.5
SO: length 1.9
  BOTTOM w0.127: U5.2 62.32,39.67 v2(61.8,39.16)
SW_50: length 0.9
  TOP w0.279: U2.22 C3.2
SWITCH_WAKEUP_B: length 19.9
  TOP w0.127: U1.5 v1(57.35,20.75)
  L3_INT_1 w0.127: TP4.1 v1(57.78,27.16)
  BOTTOM w0.127: v1(57.78,27.16) 57.78,21.18 v1(57.35,20.75)
USB1_VBUS: length 5.2
  TOP w0.127: U6.36 47.18,21.5 47.69,22 R37.2 R41.1
V_BRD: length 161.1
  TOP w0.305: R91.1 76.08,26.2 v1(76.41,25.88) 77.15,25.14 U2.16 ; v2(18.63,25.35) 18.12,24.83 U17.6 ; U20.6 v2(18.63,27.88) ; R17.1 v1(70.41,43.25)
  TOP w0.457: SH19.1 55.55,41.92 55.15,42.32 JP19.2
  L3_INT_1 w0.381: JP2.4 45.48,41.79 53.67,41.79 JP19.2
  L4_INT_2 w0.305: 20.29,42.91 19.39,42.01 19.39,33.28 18.63,32.53 v2(18.63,27.88) v2(18.63,25.35) 18.63,15.93 21.29,13.27 21.29,7.45 22.35,6.38 JS2.2
  L4_INT_2 w0.381: JP2.4 45.52,41.76 45.52,40.78 44.35,39.61 39.07,39.61 35.76,42.91 20.29,42.91 ; v1(70.41,43.25) 69.8,43.85 60.58,43.85 58.75,42.02 56.39,42.02 JP19.2 50.98,39.1 50.98,36.69 50.06,35.77 50.06,33.01 49.5,32.44 JS1.2 48.83,17.19 49.08,16.94 v2(49.08,15.72)
  BOTTOM w0.381: v1(70.41,43.25) 71.04,42.61 71.04,36.86 70.19,36 C42.1 SH12.2 72.04,34.02 73.59,32.47 73.59,29.47 74.38,28.68 76.16,28.68 76.41,28.43 C20.1 C19.1 v1(76.41,25.88)
V_LDO_OUT: length 18.3
  TOP w0.279: D1.A 31.02,40.92 ; D1.A 30.36,40.09 ; D1.A 29.7,40.92 ; D1.A 30.36,41.75 ; U4.4 27.6,43.2 ; U4.4 27.6,39.03 ; U4.4 28.92,41.11 ; U4.4 26.28,41.11 ; U4.2 21.4,41.93 ; U4.2 21.4,40.3 ; U4.2 20.08,41.11 ; U4.2 22.72,41.11 ; 29.63,38.63 C24.1 ; C24.1 30.87,39.55 ; C24.1 30.87,37.72 ; C24.1 32.1,38.63
V_SEC: length 32.1
  L3_INT_1 w0.305: JP10.2 61.21,32.98 51.39,32.98 v1(50.4,31.99)
  L4_INT_2 w0.305: v1(50.4,31.99) 50.4,18.05 JP4.2
  BOTTOM w0.305: JP6.1 JP10.2
VOUT_MLINK: length 8.8
  TOP w0.279: 12.79,11.81 U8.5 ; U8.5 12.79,13.77 ; U8.5 13.28,12.79 ; 14.82,13.4 C73.1 ; C73.1 15.61,14.06 ; C73.1 14.03,14.06 ; C74.1 17.7,14.06 ; C74.1 16.73,13.4 ; C74.1 15.75,14.06 ; 17.84,14.06 R34.1 18.63,13.4
VOUT_SWITCH: length 16.9
  TOP w0.254: U1.7 56.6,19.75 C28.1 v2(55.07,19.23)
  L4_INT_2 w0.305: v2(55.07,19.23) 55.07,21.49 55.43,21.85 55.43,23.96 54.97,24.42 54.97,30.94 JP3.3
VREF_MCULINK: length 35.7
  TOP w0.254: v1(33.92,35.34) 35.67,35.34 36.64,34.37 R42.2 ; v1(39.28,15.88) U6.17 39.28,13.68 40.05,12.91 C71.1 C70.1 40.05,10.16 39.92,10.04 R33.2 U7.1
  L4_INT_2 w0.254: v1(33.92,35.34) 36.13,33.13 36.13,30.46 39.81,26.78 39.81,17.08 39.28,16.54 v1(39.28,15.88)
VREF_OUT: length 17.4
  TOP w0.254: v1(66.76,19.75) U1.30
  BOTTOM w0.305: C15.1 v1(66.76,19.75)
  BOTTOM w0.381: TP2.1 73.53,16.71 72.8,15.98 66.02,15.98 64.81,17.2 C15.1
WP: length 2.7
  BOTTOM w0.127: U5.3 R15.2 R19.2
XTAL32K: length 3.1
  TOP w0.127: R30.2 69.67,14.34 69.99,14.03 Y2.1 C49.1
XTAL_RF: length 6.6
  TOP w0.127: v1(65.9,20.38) 65.53,20.75 U1.32
  L3_INT_1 w0.127: v1(65.9,20.38) 68.87,20.38 69.02,20.23 69.02,18.38 v2(68.57,17.94)
N22669333: length 3.8
  BOTTOM w0.127: U10.7 65.22,6.2 64.91,6.51 63.43,6.51 63.05,6.13 R63.1
N22669352: length 3.6
  BOTTOM w0.127: R64.1 63.64,5.23 63.64,6.08 63.76,6.21 64.59,6.21 64.72,6.08 U10.6
N22669391: length 6.3
  TOP w0.127: v1(52.59,11.73) 52.59,12.03 R65.1
  L3_INT_1 w0.127: v1(56.21,11.19) 53.13,11.19 v1(52.59,11.73)
  BOTTOM w0.127: U11.1 55.28,11.51 55.61,11.19 v1(56.21,11.19)
N22669418: length 14.6
  TOP w0.127: R67.1 v1(53.52,14.11) ; R65.2 51.55,13.38 JP17.1
  BOTTOM w0.127: U11.5 52.95,12.21 51.98,12.21 51.79,12.02 50.62,12.02 50.43,12.21 JP17.1 50.38,13.15 50.95,13.72 50.95,14.21 51.31,14.56 53.06,14.56 v1(53.52,14.11) 53.95,14.11 54.08,13.98 U11.9 54.08,12.94 54.23,12.79 54.65,12.79 54.88,12.56 U11.2
N22669601: length 1.1
  BOTTOM w0.127: R70.1 U12.5
N22669605: length 2.3
  BOTTOM w0.127: R68.2 R69.1 56.31,2.85 U12.4
N22669808: length 2.3
  BOTTOM w0.127: U13.4 70.54,2.85 R73.1 R72.2
N22669908: length 2.8
  TOP w0.457: D12.C 47.51,42.36 JP18.3
N22670160: length 2.8
  BOTTOM w0.127: U14.4 60.88,2.85 R78.1 R76.2
N22670341: length 1.3
  TOP w0.254: U15.4 R83.1
N22888978: length 1.8
  BOTTOM w0.127: R71.1 48.43,13.4 48.43,13.2 48.38,13.15 JP17.2
N22954457: length 2.2
  TOP w0.127: U16.3 38.73,3.63 38.35,3.25 R84.1
N22954468: length 7.3
  TOP w0.127: R101.2 42.66,1.79 42.31,1.44 39.87,1.44 39.61,1.7 R85.1 39.61,3.25 39.23,3.63 U16.4
N22954480: length 5.7
  TOP w0.127: v2(42.64,4.71) 42.64,5.53 41.99,6.18 U16.9
  BOTTOM w0.127: v2(42.64,4.71) 43.75,4.71 44.56,5.52 Q3.3
N23403057: length 2.8
  BOTTOM w0.305: JP7.2 66.97,13.24 R108.1
N23403396: length 2
  TOP w0.305: R109.1 JP6.2
N23407124: length 2.1
  TOP w0.305: D3.C 73.05,8.62 73.3,8.88 JP11.1
N23407644: length 1.1
  L3_INT_1 w0.127: v2(71.16,19.76) v2(71.16,18.71)
N23411769: length 1.2
  TOP w0.127: R1.2 62.03,13.98 C8.1
N23489789: length 18
  L4_INT_2 w0.254: J3.9 J3.8
  BOTTOM w0.241: J3.7 4.5,10.97 4.18,10.65
  BOTTOM w0.254: 4.18,10.65 1.64,10.65 J3.9 ; L9.1 J3.8 1.64,17.68 4.19,17.68 4.5,17.36 J3.6
N23489809: length 7.3
  TOP w0.254: J3.4 5.12,13.51 5.69,12.94 v1(6.21,12.94) 7.23,12.94 7.48,12.69 TP21.1
  BOTTOM w0.254: v1(6.21,12.94) 5.79,12.94 5,13.74 U9.3
N23489851: length 4
  TOP w0.241: J3.2 5.1,14.81 5.3,15.02 v2(6.21,15.02)
  BOTTOM w0.241: U9.1 5.45,14.74 5.73,15.02 v2(6.21,15.02)
N23489871: length 4
  TOP w0.241: v2(6.21,13.96) 5.3,13.96 5.1,14.16 J3.3
  BOTTOM w0.241: v2(6.21,13.96) 5.73,13.96 5.45,14.24 U9.2
N23559922: length 5.7
  TOP w0.254: U6.58 39.78,31.56 40.78,32.56 R38.2 39.89,33.61 39.25,34.24 R42.1
N23788677: length 1.2
  TOP w0.305: R98.1 18.12,23.83 U17.4
N23788861: length 4.3
  TOP w0.254: R99.1 11.42,26.63 11.87,26.18 C110.2 11.87,24.52 11.44,24.09 R45.2
N23789034: length 1.2
  TOP w0.305: U20.4 18.12,26.88 R100.1
N23802482: length 1.2
  TOP w0.305: D7.A R50.2
N23938720: length 54.3
  TOP w0.127: R84.2 v1(37.33,1.95)
  L3_INT_1 w0.127: v1(42.76,32.29) 47.3,32.29 47.99,31.61 49.31,31.61 51.85,34.15 54.02,34.15 JP13.2
  L4_INT_2 w0.127: v1(37.33,1.95) 38.15,1.95 38.61,1.48 44.23,1.48 44.86,2.12 44.86,8.47 44.27,9.06 44.27,10.46 45.04,11.24 45.04,30.01 v1(42.76,32.29)
N23938761: length 53
  TOP w0.127: R85.2 v1(40.63,1.95)
  L3_INT_1 w0.127: JP14.2 54.14,37.47 51.27,37.47 50.33,36.53 v1(44.63,36.53)
  L4_INT_2 w0.127: v1(44.63,36.53) 43.41,36.53 41.69,34.81 41.69,30.84 44.29,28.24 44.29,11.65 43.47,10.83 43.47,8.7 44.23,7.93 44.23,3.08 43.1,1.95 v1(40.63,1.95)
N23959568: length 1
  BOTTOM w0.381: R107.2 L13.1

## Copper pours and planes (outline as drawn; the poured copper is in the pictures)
1V8_DCDC on TOP: 63.42,11.62 63.6,11.44 63.6,10.3 63.45,10.15 62.75,10.15 59.6,7 56.88,7 56.4,7.48 56.4,9.51 56.7,9.81 59.9,9.81 60.26,10.17 60.26,10.84 60.55,11.14 61.34,11.14 61.34,11.62
GND on TOP: 0.56,44.44 84.56,44.44 99.44,29.56 99.44,15.44 84.56,0.56 0.56,0.56 ; 28 cut-outs
GND on BOTTOM: 0.56,44.44 84.56,44.44 99.44,29.56 99.44,15.44 84.56,0.56 0.56,0.56 ; 12 cut-outs
GND on L2_GND_1: 0.56,44.44 84.56,44.44 99.44,29.56 99.44,15.44 84.56,0.56 0.56,0.56 ; 2 cut-outs
GND on L3_INT_1: 0.56,44.44 84.56,44.44 99.44,29.56 99.44,15.44 84.56,0.56 0.56,0.56 ; 26 cut-outs
GND on L4_INT_2: 0.56,44.44 84.56,44.44 99.44,29.56 99.44,15.44 84.56,0.56 0.56,0.56 ; 12 cut-outs
GND on L5_GND_2: 0.56,44.44 84.56,44.44 99.44,29.56 99.44,15.44 84.56,0.56 0.56,0.56 ; 1 cut-out
P3V3_BATT on TOP: 37.55,39.43 37.55,37.43 36.93,36.81 36.93,36.81 35.4,36.81 35.4,39.43 35.68,39.71 37.27,39.71
P3V3_BATT on BOTTOM: 35.84,41.03 40.77,41.03 41.1,40.7 41.1,32.65 40.67,32.22 35.94,32.22 35.31,32.85 35.31,40.5
P5V on TOP: 20.07,39.84 22.74,39.84 23.05,39.53 23.05,38.06 21.85,36.86 21.85,35.59 23.04,34.41 23.04,33.38 22.66,33 20.53,33 19.87,33.66 19.87,39.63
P5V on BOTTOM: 20.8,34.83 20.8,32.88 22.96,32.88 22.96,34.83
P5V_CAN on TOP: 16.37,44.18 14.61,44.18 14.41,43.98 14.41,40.04 13.16,38.79 13.16,35.01 13.75,34.43 18.47,34.43 19.26,35.21 19.26,38.29 18.47,39.07 17.51,39.07 16.54,40.04 16.54,44
P5V_CAN on BOTTOM: 17.75,37.73 19.41,37.73 19.69,37.45 19.69,33.31 19.25,32.88 17.81,32.88 17.48,33.21 17.48,37.45
P12V on BOTTOM: 8.05,35.33 14.05,35.33 14.5,34.88 14.5,33.72 14.21,33.43 8.04,33.43 7.69,33.78 7.69,34.98
P12V on L4_INT_2: 12.3,33.13 11.92,32.75 6.71,32.75 6.28,32.32 6.28,22.89 5.44,22.06 2.98,22.06 2.24,22.79 2.24,24.04 3.11,24.9 4.3,24.9 4.81,25.41 4.81,34.4 5.77,35.37 11.84,35.37 12.3,34.91
P12V_VBAT on BOTTOM: 12.03,38.92 12.03,36.27 12.46,35.84 13.68,35.84 13.83,36 13.83,37.74 13.72,37.85 13.72,43.5 13.47,43.75 12.73,43.75 12.42,43.44 12.42,39.31
VBAT_DCDC/VBAT_PMU on TOP: 43.46,37.37 41.45,37.37 41.33,37.25 41.33,36.46 41.5,36.28 42.82,36.28 43.34,35.76 43.34,31.71 43.14,31.5 43.14,28.36 43.63,27.86 45.78,27.86 45.78,28.14 45.05,28.14 44.99,28.2 44.99,28.3 45.05,28.36 45.78,28.36 45.78,28.64 45.05,28.64 44.94,28.75 44.94,35.87 44.96,35.87
VCC_IF_LINK on BOTTOM: 65.58,4.75 66.24,4.75 66.51,5.02 67.47,5.02 67.68,5.23 67.68,5.73 67.3,6.12 66.01,6.12 65.84,5.97 65.58,5.97
VDD_MEM on BOTTOM: 65.87,39.33 66.74,39.33 66.99,39.07 66.99,38.57 67.45,38.11 68.18,38.11 68.62,37.68 68.62,37.14 68.31,36.84 67.5,36.84 66.79,37.55 65.21,37.55 65.01,37.35 65.01,36.76 64.63,36.38 63.2,36.38 62.95,36.64 62.95,37.37 63.18,37.6 63.79,37.6 64.42,38.24 64.42,38.67 64.65,38.9 65.44,38.9
ANT_A on TOP: 99.28,43.01 98.01,44.28 95.18,41.46 96.45,40.18
ANT_B on TOP: 99.28,1.99 98.01,0.72 95.18,3.55 96.45,4.82
DCDC_LX on TOP (solid shape): 63.03,14.75 63.03,13.32 63.35,13.01 63.35,12.28 61.95,12.28 61.95,13.42 62.06,13.52 62.28,13.52 62.43,13.67 62.43,14.38 62.22,14.59 62.22,15.25 62.32,15.36 62.42,15.36
FL_USB_5V0 on TOP: 6.61,19.97 6.61,17.59 6.74,17.46 6.74,17.13 7.2,16.67 8.36,16.67 8.58,16.89 12.19,16.89 12.48,16.59 12.48,14.71 12.68,14.51 13.72,14.51 14,14.79 14,16.9 14.46,17.36 14.46,17.97 13.88,18.55 9.53,18.55 9.51,18.52 9.02,19.01 9.02,19.97 8.69,20.3 6.94,20.3
MCU_LINK_3V3 on TOP: 28.78,16.64 30.23,16.64 30.23,14.16 29.05,12.99 28.79,12.99 28.53,12.73 28.53,12.07 28.4,11.95 27.82,11.95 27.67,12.1 27.67,12.68 27.36,12.99 21.91,12.99 21.59,13.31 21.59,14.65 21.78,14.84 23.38,14.84 23.68,14.54 26.86,14.54 27.26,14.94 28.48,14.94 28.78,15.24
MCU_LINK_3V3 on TOP: 43.14,14 44.89,14 45.04,13.85 46.82,13.85 47.05,14.08 47.05,14.51 46.79,14.77 45.32,14.77 44.64,15.45 43.14,15.45
MLINK_3V3 on TOP: 18.01,15.4 18.39,15.02 19.55,15.02 19.97,15.44 23.14,15.44 23.31,15.61 23.31,16.94 23.68,17.31 24.39,17.31 24.75,17.66 24.75,18.98 24.65,19.08 23.48,19.08 23.27,18.88 23.27,17.92 23.2,17.84 20.96,17.84 19.85,18.96 19.85,21.22 19.62,21.45 19.16,21.45 18.96,21.24 18.96,18.96 18.01,18.01
MLINK_3V3 on BOTTOM: 65.58,2.97 66.24,2.97 66.51,2.7 67.47,2.7 67.68,2.5 67.68,1.99 67.3,1.61 66.01,1.61 65.84,1.75 65.58,1.75
V_LDO_OUT on TOP: 20.1,42.15 24.7,42.15 26.07,43.52 29.57,43.52 31.28,41.82 31.28,40.55 32.32,39.51 32.32,37.73 32.09,37.5 27.13,37.5 25.74,38.9 25.74,39.78 25.43,40.09 20.05,40.09 19.87,40.27 19.87,41.92
VOUT_MLINK on TOP: 12.35,13.82 12.35,11.71 12.64,11.42 13.35,11.42 14.69,12.76 18.55,12.76 19.08,13.29 19.08,14.33 18.85,14.56 14.38,14.56 13.84,14.02 13.61,14.02 13.6,14.02 12.56,14.02

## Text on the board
BOTTOM: 170-50702 REV C | 09 | L6_SS
Board Geometry/Soldermask Bottom: 10 | SECONDARY SOLDERMASK
Ref Des/Silkscreen Bottom: D | ANTENNA CONTROL | CTL1 | H | L | CTL2 | CTL3 | MODE | RF1 | RF2 | RF3 | RF4 | OFF | SMA1 | ANT_A | ANT_B | SMA2 | SN | 700 | SCH | 11 | SECONDARY SILKSCREEN
User.Comments: 1 OF 1 | TEST PROBE | 1/1 | 1 | 2
TOP: 04 | L1_PS
Board Geometry/Soldermask Top: 03 | PRIMARY SOLDERMASK
Ref Des/Silkscreen Top: B | A | TARGET | C | JP10 VDD_BRD | 1-2 | DCDC MODE | 2-3 | BYPASS MODE | KW45B41Z-LOC | 02 | PRIMARY SILKSCREEN
L2_GND_1: 05 | L2_GND_1
L3_INT_1: 06 | L3_INT_1
L4_INT_2: 07 | L4_INT_2
L5_GND_2: 08 | L5_GND_2
XSECTION_CHART: L4_INT_2 | L3_INT_1 | LAYERS | L1_PS | L6_SS | TRACE WIDTH | N/A | 5.00 | SE | IMPEDANCE | 50.00 | 4.00 | 9.50 | TRACE SPACING | 7.00 | 6.50 | 100.00 | 90.00 | REFERENCE LAYER | 2/4 | 5 | 2 | DIFF | 11.00 | 12.00 | COPLANAR | 6.00 | GAP | BOARD THICKNESS TOLERANCE +/-10% | SCALE: NONE | 16 | 22 | INTENTIONAL 18 SHORTS AT: | LocationStart         LocationEnd       RefDes       Net 1           Net 2 | (100.00 110.00)       (100.00 70.00)    SH5          PTC7            LLWU/NMI_B | (40.00 -70.00)        (0.00 -70.00)     SH3          PTD2/TMP1_CH0   PWM/TMP1_CH0 | (0.00 833.00)         (0.00 793.00)     SH2          ADC_IN          ADC0_A13 | (100.00 833.00)       (100.00 793.00)   SH1          RESET           RST_TGTMCU_B | (300.00 110.00)       (300.00 70.00)    SH9          PTA17           LPUART0_TX | (200.00 110.00)       (200.00 70.00)    SH7          PTA16           LPUART0_RX | (300.00 833.00)       (300.00 793.00)   SH6          LPSPI1_SCK      PTB2 | (200.00 833.00)       (200.00 793.00)   SH4          LPSPI1_PSC0     PTB0 | (521.26 -140.00)      (600.00 -140.00)  JS2          P_LED           V_BRD | (460.00 -73.03)       (500.00 -73.03)   SH13         PTD3/I2C1_SDA   LPI2C1_SDA | (400.00 110.00)       (400.00 70.00)    SH11         PTB5            LPI2C1_SCL | (400.00 833.00)       (440.00 833.00)   SH8          LPSPI1_SIN      PTB1 | (500.00 833.00)       (540.00 833.00)   SH10         LPSPI1_SOUT     PTB3 | (600.00 110.00)       (600.00 70.00)    SH14         P5V             5V_MIKROE | (1652.41 275.60)      (1692.41 275.60)  SH15         V_BRD           VCC_TGMCU | (1642.41 1012.71)     (1642.41 933.97)  JS1          VDD_MEM         V_BRD | (1969.89 1280.00)     (1906.89 1280.00) SH19         P3V3_LDO        V_BRD | (2483.41 955.97)      (2483.41 995.97)  SH12         3V3_MIKROE      V_BRD | *  SURFACE - AIR 0 MIL | *  DIELECTRIC - DRY_FILM_MASK 0.8 MIL | L1 TOP CONDUCTOR - COPPER 2.1 MIL | *  DIELECTRIC - FR-4 9.637 MIL | L2 L2_GND PLANE - COPPER 1.25 MIL | *  DIELECTRIC - FR-4 14 MIL | L3 L3_IN1 CONDUCTOR - COPPER 1.25 MIL | *  DIELECTRIC - FR-4 4.35 MIL | L4 L4_PWR PLANE - COPPER 1.25 MIL | L5 L5_GND PLANE - COPPER 1.25 MIL | *  DIELECTRIC - FR-4 9.639 MIL | L6 BOTTOM CONDUCTOR - COPPER 2.1 MIL | DESIGN CROSS SECTION CHART | ___________________________ | TOTAL THICKNESS 62.426 MIL | 1-6 | 19 | *IMPEDANCE TABLE VALUES ARE BASED ON THE FAB VENDOR SUPPLIED STACK-UP | IF ANY IMPEDANCE IS NOT FOUND ON A SPECIFIC LAYER, PLEASE IGNORE IT | DETAIL | IMPEDANCE REQUIREMENTS | IMPEDANCE TOLERANCE IS 10% | LAYER STACKUP | B | A
DIMENSION: PRIMARY DATUM | GRID ORIGIN
BODY_CENTER: 01 | PRIMARY PASTEMASK
DISPLAY_BOTTOM: 12 | SECONDARY PASTEMASK
COMPVAL_TYPE_TOP: OF 12
User.8: 22. THIS FAB_VIAFILL.ART SHOWS LOCATIONS OF VIA-IN-PAD TO BE FILLED. | 1/1 | 2
User.9: 1/1 | 3
User.10: 05-25-22 | 02-02-23 | A.Q. | J.C. | E.L. | B | C | SECOND RELEASE | THIRD RELEASE | A
User.15: FIGURE | FINISHED_SIZE | 100.0 | 8.0 | 8.1 | 26.0 | 35.0 | 40.0 | 33.0x26.0 | 59.0x32.0 | 111.0x32.0 | 122.0x32.0 | DRILL CHART: TOP to BOTTOM | ALL UNITS ARE IN MILS | TOLERANCE_DRILL | +2.0/-2.0 | +0.0/-8.0 | +0.0/-8.1 | +3.0/-3.0 | PLATED | NON-PLATED | QTY | 1 | 1832 | 164 | 20 | 48 | 4 | 30 | 2 | 3
